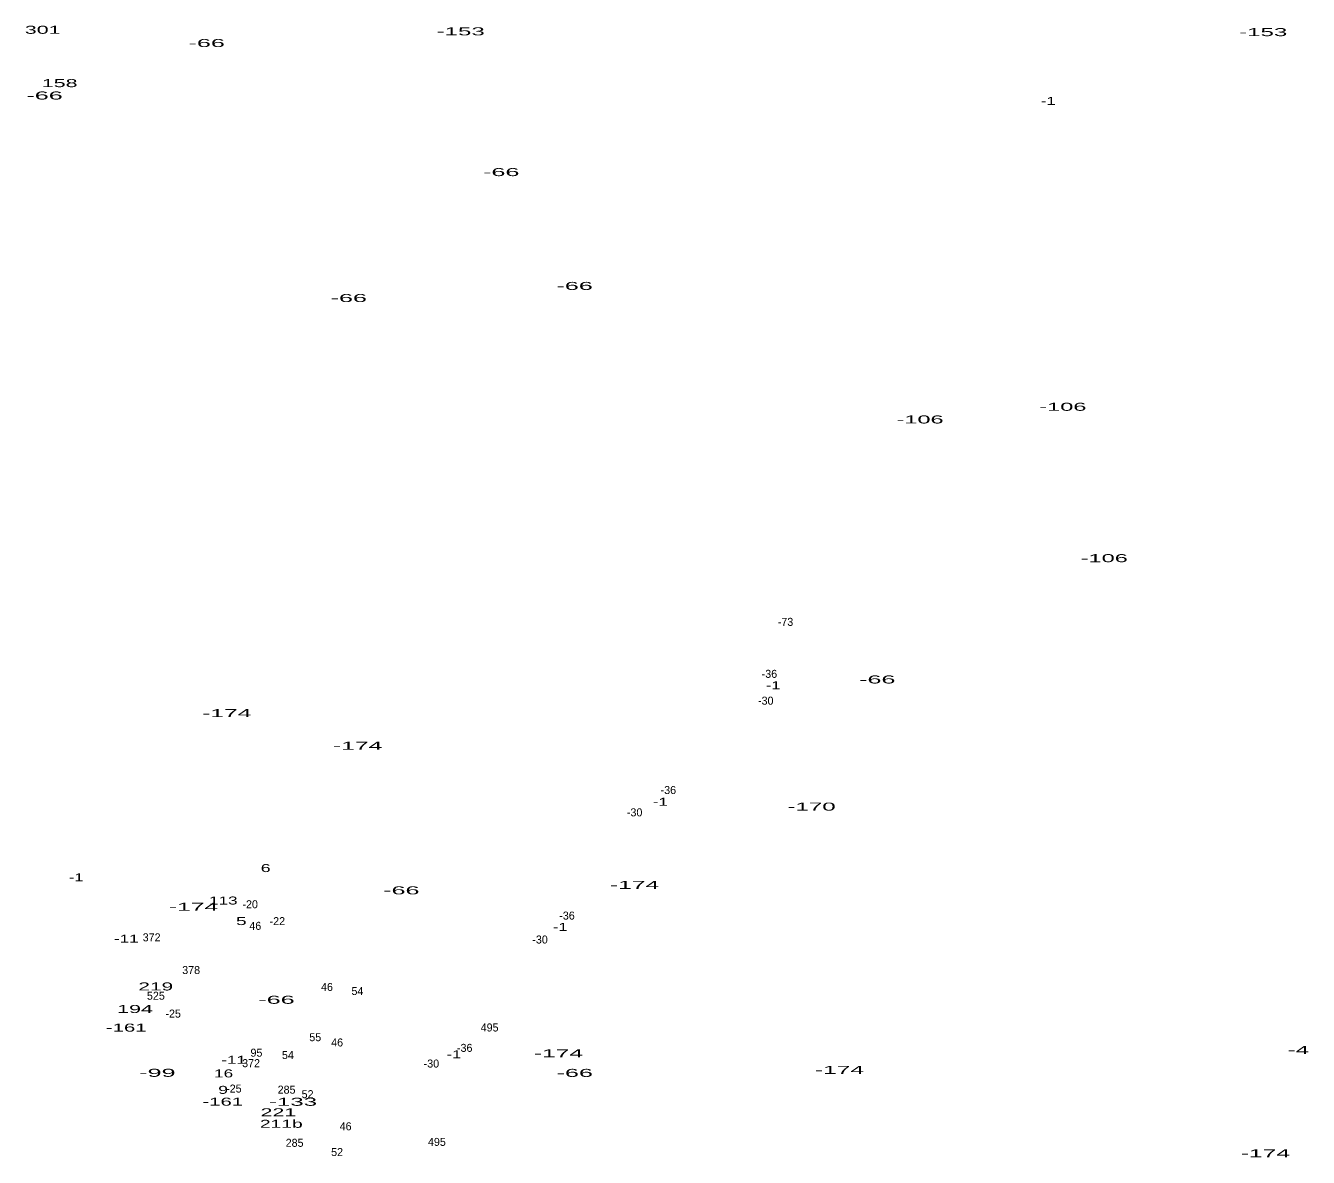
# Model space of a CAD drawing. Extents: x -662280 to -658689, y -991723 to -987042.
# Drawn here: x -661638 to -660997, y -990573 to -990007 of the extents above; entities that cross this region are included whole.
import ezdxf
from ezdxf.enums import TextEntityAlignment as Align

# ---------------------------------------------------------------- set-up
doc = ezdxf.new("R2010")
doc.units = 0
doc.header["$LTSCALE"] = 1.6
doc.layers.add('24', color=7, linetype='Continuous')

msp = doc.modelspace()

# ---------------------------------------------------------------- texts
at = {"layer": '24'}
for s, width, p in [('301', 2, (-661629.944, -990011.42)), ('-153', 2.25, (-661420.971, -990012.21)), ('-153', 2.25, (-661019.761, -990012.59)), ('-66', 2.35, (-661547.943, -990018.05)), ('158', 2, (-661621.447, -990038.09)), ('-66', 2.35, (-661628.993, -990044.28)), ('-1', 1.55, (-661127.201, -990046.94)), ('-66', 2.35, (-661400.693, -990082.55)), ('-66', 2.35, (-661363.993, -990139.45)), ('-66', 2.35, (-661476.913, -990145.5)), ('-106', 2.2, (-661119.921, -990199.85)), ('-106', 2.2, (-661191.311, -990206.19)), ('-106', 2.2, (-661099.221, -990275.52)), ('-1', 1.55, (-661264.751, -990339.04)), ('-66', 2.35, (-661212.693, -990336.15)), ('-174', 2.3, (-661537.931, -990352.98)), ('-174', 2.3, (-661472.481, -990369.27)), ('-1', 1.55, (-661321.131, -990397.29)), ('-170', 2.25, (-661245.551, -990399.7)), ('6', 1.65, (-661518.466, -990430.41)), ('-1', 1.55, (-661613.201, -990435.04)), ('-66', 2.35, (-661450.643, -990441.56)), ('-174', 2.3, (-661334.031, -990438.82)), ('-174', 2.3, (-661554.551, -990449.77)), ('113', 1.6, (-661539.634, -990446.64)), ('5', 1.8, (-661530.661, -990456.9)), ('-1', 1.55, (-661371.191, -990459.81)), ('-11', 1.6, (-661588.127, -990465.7)), ('219', 1.95, (-661573.433, -990489.58)), ('194', 2, (-661583.788, -990500.86)), ('-66', 2.35, (-661513.053, -990496.24)), ('-161', 1.9, (-661588.171, -990510.16)), ('-11', 1.6, (-661534.487, -990526.25)), ('-1', 1.55, (-661424.361, -990523.5)), ('-174', 2.3, (-661372.091, -990523.01)), ('-4', 2.25, (-661002.19, -990521.35)), ('-99', 2.35, (-661572.623, -990532.74)), ('16', 1.6, (-661539.493, -990533.05)), ('-66', 2.35, (-661363.943, -990532.8)), ('-174', 2.3, (-661231.611, -990531.3)), ('9', 1.65, (-661539.746, -990541.28)), ('-161', 1.9, (-661539.911, -990547.17)), ('221', 2, (-661512.097, -990552.49)), ('-133', 2.25, (-661504.811, -990547.22)), ('211b', 1.8, (-661510.639, -990558.23)), ('-174', 2.3, (-661018.671, -990573))]:
    msp.add_text(s, height=4, dxfattribs=dict(at, width=width)).set_placement(p, align=Align.CENTER)
for s, p in [('-73', (-661258.571, -990307.35)), ('-36', (-661266.63, -990333.33)), ('-30', (-661268.449, -990346.74)), ('-36', (-661317.15, -990391.41)), ('-30', (-661334.009, -990402.57)), ('-20', (-661526.209, -990448.5)), ('-36', (-661367.82, -990454.17)), ('46', (-661523.657, -990459.3)), ('-22', (-661512.645, -990456.94)), ('372', (-661575.493, -990465.03)), ('-30', (-661381.289, -990466.13)), ('378', (-661555.733, -990481.39)), ('525', (-661573.367, -990494.22)), ('46', (-661487.817, -990489.84)), ('54', (-661472.601, -990491.87)), ('-25', (-661564.715, -990503.15)), ('495', (-661406.507, -990510.09)), ('495', (-661406.507, -990510.09)), ('55', (-661493.667, -990514.95)), ('46', (-661482.737, -990517.57)), ('-36', (-661418.95, -990520.28)), ('95', (-661523.083, -990522.7)), ('54', (-661507.351, -990523.87)), ('372', (-661525.773, -990527.93)), ('-30', (-661435.609, -990528.12)), ('-25', (-661534.355, -990540.62)), ('285', (-661508.017, -990541.18)), ('52', (-661497.507, -990543.43)), ('46', (-661478.497, -990559.48)), ('285', (-661503.997, -990567.74)), ('495', (-661432.867, -990567.28)), ('52', (-661482.777, -990572.36))]:
    msp.add_text(s, height=4, dxfattribs=at).set_placement(p, align=Align.CENTER)

doc.saveas('drawing.dxf')
